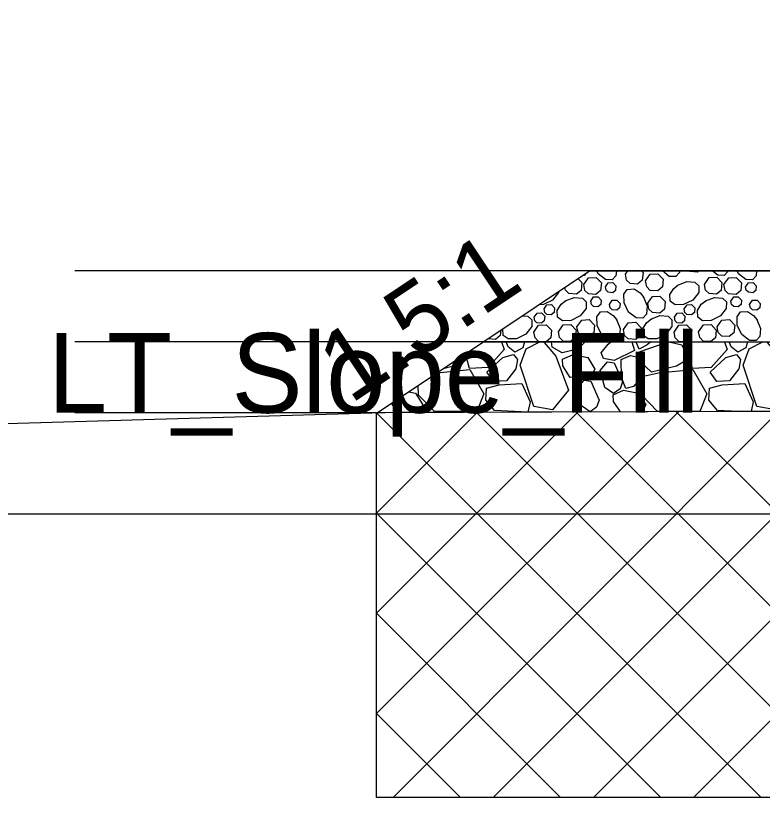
# Model space of a CAD drawing. Extents: x -14026 to 1303, y -10 to 9533.
# Drawn here: x 108.61 to 119.15, y 3996 to 4007.03 of the extents above; entities that cross this region are included whole.
import ezdxf

# ---------------------------------------------------------------- set-up
doc = ezdxf.new("R2010")
doc.units = 0
for name, color, linetype in [('Exist Cross Section Cell', 7, 'Continuous'), ('Exist XS Ground Line', 7, 'Continuous'), ('Old_Level_10', 7, 'Continuous'), ('Prop XS Side Slope Text', 7, 'Continuous'), ('Scratch_Level_0', 7, 'Continuous'), ('Scratch_Level_3', 7, 'Continuous'), ('Scratch_Level_5', 7, 'Continuous')]:
    doc.layers.add(name, color=color, linetype=linetype)

msp = doc.modelspace()

# ---------------------------------------------------------------- linework, layer by layer
at = {"layer": 'Exist Cross Section Cell'}
msp.add_line((0, 4000), (150, 4000), dxfattribs=at)
at = {"layer": 'Exist XS Ground Line'}
msp.add_lwpolyline([(103.803, 4001.139), (113.961, 4001.433), (121.109, 4001.453), (122.206, 4001.557), (124.865, 4002.502), (128.249, 4003.656), (131.147, 4004.565), (132.692, 4005.022), (133.861, 4005.345), (137.453, 4006.434), (141.559, 4006.646), (143.818, 4006.925), (150, 4006.975), (154.881, 4007.014), (166.19, 4007.028)], dxfattribs=at)
at = {"layer": 'Old_Level_10'}
for p, q in [((117.217, 4003.38), (117.249, 4003.426)), ((115.211, 4002.426), (124.649, 4002.426)), ((114.931, 4002.238), (114.955, 4002.182)), ((114.006, 4001.427), (113.915, 4001.561))]:
    msp.add_line(p, q, dxfattribs=at)
msp.add_lwpolyline([(121.109, 4001.453), (113.711, 4001.425), (116.711, 4003.426), (127.573, 4003.426), (122.206, 4001.557)], close=True, dxfattribs=at)
for points in [[(117.09, 4003.426), (117.084, 4003.358), (117.032, 4003.303), (116.938, 4003.305), (116.832, 4003.388), (116.813, 4003.426)], [(117.445, 4003.426), (117.466, 4003.404), (117.455, 4003.296), (117.389, 4003.24), (117.283, 4003.248), (117.233, 4003.296), (117.217, 4003.38)], [(117.983, 4003.426), (117.981, 4003.403), (117.929, 4003.348), (117.835, 4003.35), (117.738, 4003.426)], [(118.253, 4003.426), (118.234, 4003.41), (118.128, 4003.417), (118.12, 4003.426)], [(118.665, 4003.426), (118.664, 4003.419), (118.612, 4003.364), (118.519, 4003.366), (118.442, 4003.426)], [(119.069, 4003.426), (119.063, 4003.358), (119.011, 4003.303), (118.917, 4003.305), (118.811, 4003.388), (118.792, 4003.426)], [(116.548, 4003.317), (116.602, 4003.262), (116.591, 4003.153), (116.525, 4003.098), (116.419, 4003.106), (116.369, 4003.154), (116.361, 4003.192)], [(116.658, 4003.39), (116.634, 4003.364), (116.62, 4003.364)], [(116.629, 4003.233), (116.696, 4003.329), (116.804, 4003.335), (116.878, 4003.258), (116.867, 4003.149), (116.801, 4003.094), (116.695, 4003.102), (116.645, 4003.15), (116.629, 4003.233)], [(117.501, 4003.285), (117.568, 4003.38), (117.675, 4003.386), (117.75, 4003.309), (117.739, 4003.201), (117.673, 4003.145), (117.567, 4003.153), (117.517, 4003.201), (117.501, 4003.285)], [(118.331, 4003.237), (118.398, 4003.333), (118.506, 4003.339), (118.58, 4003.262), (118.57, 4003.153), (118.503, 4003.098), (118.397, 4003.106), (118.347, 4003.154), (118.331, 4003.237)], [(118.608, 4003.233), (118.675, 4003.329), (118.782, 4003.335), (118.857, 4003.258), (118.846, 4003.149), (118.78, 4003.094), (118.674, 4003.102), (118.624, 4003.15), (118.608, 4003.233)], [(116.935, 4003.204), (116.975, 4003.261), (117.04, 4003.265), (117.084, 4003.218), (117.078, 4003.153), (117.038, 4003.12), (116.975, 4003.125), (116.945, 4003.154), (116.935, 4003.204)], [(117.956, 4003.228), (118.082, 4003.278), (118.197, 4003.268), (118.252, 4003.216), (118.251, 4003.122), (118.167, 4003.016), (118.038, 4002.951), (117.917, 4002.949), (117.849, 4002.998), (117.842, 4003.095), (117.898, 4003.181), (117.961, 4003.232)], [(118.914, 4003.204), (118.954, 4003.261), (119.018, 4003.265), (119.063, 4003.218), (119.057, 4003.153), (119.017, 4003.12), (118.953, 4003.125), (118.923, 4003.154), (118.914, 4003.204)], [(116.272, 4003.133), (116.272, 4003.122), (116.189, 4003.016), (116.06, 4002.951), (115.999, 4002.95)], [(117.474, 4003.058), (117.524, 4002.933), (117.514, 4002.817), (117.461, 4002.762), (117.368, 4002.764), (117.261, 4002.847), (117.197, 4002.976), (117.195, 4003.097), (117.243, 4003.166), (117.34, 4003.172), (117.426, 4003.117), (117.477, 4003.053)], [(116.368, 4003.004), (116.493, 4003.054), (116.609, 4003.044), (116.664, 4002.991), (116.662, 4002.898), (116.579, 4002.791), (116.45, 4002.727), (116.329, 4002.725), (116.26, 4002.773), (116.254, 4002.87), (116.309, 4002.956), (116.373, 4003.007)], [(116.727, 4003.002), (116.767, 4003.059), (116.832, 4003.063), (116.876, 4003.016), (116.87, 4002.951), (116.83, 4002.918), (116.766, 4002.923), (116.737, 4002.952), (116.727, 4003.002)], [(116.992, 4002.955), (117.032, 4003.012), (117.096, 4003.016), (117.141, 4002.969), (117.135, 4002.904), (117.095, 4002.871), (117.031, 4002.876), (117.001, 4002.905), (116.992, 4002.955)], [(117.531, 4002.97), (117.598, 4003.066), (117.705, 4003.072), (117.78, 4002.994), (117.769, 4002.886), (117.703, 4002.831), (117.597, 4002.838), (117.547, 4002.887), (117.531, 4002.97)], [(118.346, 4003.004), (118.472, 4003.054), (118.588, 4003.044), (118.643, 4002.991), (118.641, 4002.898), (118.557, 4002.791), (118.429, 4002.727), (118.307, 4002.725), (118.239, 4002.773), (118.233, 4002.87), (118.288, 4002.956), (118.351, 4003.007)], [(118.706, 4003.002), (118.746, 4003.059), (118.81, 4003.063), (118.855, 4003.016), (118.849, 4002.951), (118.809, 4002.918), (118.745, 4002.923), (118.715, 4002.952), (118.706, 4003.002)], [(118.97, 4002.955), (119.011, 4003.012), (119.075, 4003.016), (119.12, 4002.969), (119.113, 4002.904), (119.074, 4002.871), (119.01, 4002.876), (118.98, 4002.905), (118.97, 4002.955)], [(116.068, 4002.891), (116.108, 4002.949), (116.173, 4002.953), (116.217, 4002.906), (116.211, 4002.841), (116.171, 4002.808), (116.108, 4002.813), (116.078, 4002.842), (116.068, 4002.891)], [(118.047, 4002.891), (118.087, 4002.949), (118.151, 4002.953), (118.196, 4002.906), (118.19, 4002.841), (118.15, 4002.808), (118.086, 4002.813), (118.056, 4002.842), (118.047, 4002.891)], [(115.764, 4002.794), (115.84, 4002.787), (115.895, 4002.735), (115.894, 4002.642), (115.81, 4002.535), (115.681, 4002.471), (115.56, 4002.468), (115.492, 4002.517), (115.486, 4002.608)], [(115.929, 4002.775), (115.97, 4002.832), (116.034, 4002.836), (116.079, 4002.789), (116.072, 4002.724), (116.033, 4002.691), (115.969, 4002.696), (115.939, 4002.725), (115.929, 4002.775)], [(117.093, 4002.741), (117.143, 4002.615), (117.133, 4002.5), (117.081, 4002.445), (116.987, 4002.447), (116.881, 4002.53), (116.816, 4002.659), (116.814, 4002.78), (116.863, 4002.849), (116.959, 4002.855), (117.046, 4002.8), (117.096, 4002.736)], [(117.578, 4002.748), (117.704, 4002.797), (117.819, 4002.787), (117.874, 4002.735), (117.872, 4002.642), (117.789, 4002.535), (117.66, 4002.471), (117.539, 4002.468), (117.47, 4002.517), (117.464, 4002.614), (117.519, 4002.7), (117.583, 4002.751)], [(117.908, 4002.775), (117.948, 4002.832), (118.013, 4002.836), (118.057, 4002.789), (118.051, 4002.724), (118.011, 4002.691), (117.948, 4002.696), (117.918, 4002.725), (117.908, 4002.775)], [(119.072, 4002.741), (119.122, 4002.615), (119.112, 4002.5), (119.06, 4002.445), (118.966, 4002.447), (118.859, 4002.53), (118.795, 4002.659), (118.793, 4002.78), (118.841, 4002.849), (118.938, 4002.855), (119.025, 4002.8), (119.075, 4002.736)], [(115.925, 4002.565), (115.992, 4002.66), (116.099, 4002.666), (116.174, 4002.589), (116.163, 4002.481), (116.097, 4002.426), (115.991, 4002.433), (115.941, 4002.482), (115.925, 4002.565)], [(116.272, 4002.569), (116.339, 4002.664), (116.446, 4002.67), (116.521, 4002.593), (116.51, 4002.485), (116.444, 4002.429), (116.338, 4002.437), (116.288, 4002.486), (116.272, 4002.569)], [(116.532, 4002.639), (116.6, 4002.734), (116.707, 4002.741), (116.782, 4002.663), (116.771, 4002.555), (116.704, 4002.5), (116.598, 4002.507), (116.549, 4002.556), (116.532, 4002.639)], [(117.19, 4002.6), (117.257, 4002.696), (117.365, 4002.702), (117.439, 4002.625), (117.428, 4002.516), (117.362, 4002.461), (117.256, 4002.469), (117.206, 4002.517), (117.19, 4002.6)], [(117.903, 4002.565), (117.971, 4002.66), (118.078, 4002.666), (118.153, 4002.589), (118.142, 4002.481), (118.076, 4002.426), (117.97, 4002.433), (117.92, 4002.482), (117.904, 4002.565)], [(118.25, 4002.569), (118.318, 4002.664), (118.425, 4002.67), (118.5, 4002.593), (118.489, 4002.485), (118.422, 4002.429), (118.316, 4002.437), (118.267, 4002.486), (118.25, 4002.569)], [(118.511, 4002.639), (118.578, 4002.734), (118.686, 4002.741), (118.76, 4002.663), (118.749, 4002.555), (118.683, 4002.5), (118.577, 4002.507), (118.527, 4002.556), (118.511, 4002.639)], [(115.457, 4002.589), (115.45, 4002.516), (115.383, 4002.461), (115.277, 4002.469), (115.277, 4002.469)], [(115.468, 4002.426), (115.507, 4002.319), (115.28, 4002.066), (115.018, 4002.049), (114.958, 4002.257)], [(115.657, 4002.281), (115.561, 4002.358), (115.536, 4002.426)], [(115.792, 4002.426), (115.768, 4002.342), (115.657, 4002.281)], [(116.069, 4002.419), (116.233, 4002.225), (116.415, 4001.745), (116.189, 4001.467), (115.924, 4001.512), (115.732, 4002.099), (115.816, 4002.327), (116.007, 4002.426)], [(116.651, 4002.426), (116.54, 4002.322), (116.323, 4002.27), (116.182, 4002.351), (116.176, 4002.426)], [(116.873, 4002.273), (116.974, 4002.395), (117.013, 4002.426)], [(117.307, 4002.426), (117.347, 4002.304), (117.06, 4002.162), (116.909, 4002.192), (116.873, 4002.273)], [(117.413, 4002.321), (117.372, 4002.413), (117.366, 4002.426)], [(117.576, 4002.426), (117.524, 4002.382), (117.413, 4002.321)], [(118.103, 4002.182), (117.938, 4002.082), (117.585, 4001.999), (117.429, 4002.143), (117.423, 4002.292), (117.818, 4002.426)], [(117.833, 4002.426), (118.013, 4002.385), (118.103, 4002.182)], [(118.616, 4002.426), (118.655, 4002.319), (118.427, 4002.066), (118.165, 4002.049), (118.058, 4002.426)], [(118.805, 4002.281), (118.708, 4002.358), (118.683, 4002.426)], [(118.939, 4002.426), (118.915, 4002.342), (118.805, 4002.281)], [(119.217, 4002.419), (119.381, 4002.225), (119.563, 4001.745), (119.336, 4001.467), (119.072, 4001.512), (118.879, 4002.099), (118.964, 4002.327), (119.155, 4002.426)], [(115.695, 4002.176), (115.672, 4002.045), (115.538, 4001.876), (115.361, 4001.868), (115.263, 4001.998), (115.485, 4002.205), (115.636, 4002.249), (115.695, 4002.176)], [(116.33, 4002.183), (116.478, 4002.246), (116.686, 4002.204), (116.786, 4002.039), (116.734, 4001.943), (116.435, 4001.925), (116.334, 4002.09), (116.33, 4002.183)], [(117.223, 4001.768), (117.162, 4001.922), (117.157, 4002.177), (117.29, 4002.236), (117.375, 4002.213), (117.413, 4001.89), (117.329, 4001.797), (117.223, 4001.768)], [(118.843, 4002.176), (118.819, 4002.045), (118.685, 4001.876), (118.509, 4001.868), (118.411, 4001.998), (118.632, 4002.205), (118.784, 4002.249), (118.843, 4002.176)], [(114.955, 4002.182), (114.791, 4002.082), (114.644, 4002.047)], [(117.05, 4001.698), (116.928, 4001.781), (116.861, 4002.022), (116.963, 4002.145), (117.057, 4002.13), (117.175, 4001.86), (117.141, 4001.765), (117.05, 4001.698)], [(114.559, 4001.991), (115.023, 4002.034), (115.218, 4001.691), (115.122, 4001.443), (114.521, 4001.444), (114.299, 4001.673), (114.29, 4001.812)], [(117.43, 4001.935), (117.684, 4001.989), (118.17, 4002.034), (118.366, 4001.691), (118.269, 4001.443), (117.669, 4001.444), (117.447, 4001.673), (117.43, 4001.935)], [(116.72, 4001.44), (116.598, 4001.523), (116.532, 4001.764), (116.633, 4001.887), (116.728, 4001.872), (116.845, 4001.602), (116.811, 4001.506), (116.72, 4001.44)], [(115.257, 4001.774), (115.436, 4001.819), (115.755, 4001.838), (115.871, 4001.58), (115.84, 4001.435), (115.37, 4001.46), (115.245, 4001.605), (115.257, 4001.774)], [(118.805, 4001.444), (118.517, 4001.46), (118.393, 4001.605), (118.404, 4001.774)], [(118.404, 4001.774), (118.584, 4001.819), (118.902, 4001.838), (119.019, 4001.58), (118.99, 4001.445)], [(114.158, 4001.723), (114.252, 4001.704), (114.359, 4001.54), (114.306, 4001.444), (114.026, 4001.427)], [(117.044, 4001.677), (117.192, 4001.746), (117.4, 4001.704), (117.506, 4001.54), (117.454, 4001.444), (117.378, 4001.439)], [(117.146, 4001.438), (117.048, 4001.584), (117.044, 4001.677)]]:
    msp.add_lwpolyline(points, dxfattribs=at)
at = {"layer": 'Scratch_Level_3'}
for p, q in [((127.573, 4003.426), (109.446, 4003.426)), ((116.708, 4002.426), (109.446, 4002.426)), ((113.705, 4001.426), (109.446, 4001.426))]:
    msp.add_line(p, q, dxfattribs=at)
at = {"layer": 'Scratch_Level_5'}
for p, q in [((113.705, 3997.183), (117.964, 4001.441)), ((113.705, 3998.597), (116.544, 4001.436)), ((113.705, 4000.011), (115.125, 4001.431)), ((113.705, 4001.426), (119.131, 3996)), ((113.937, 3996), (119.383, 4001.447)), ((115.114, 4001.431), (120.545, 3996)), ((115.351, 3996), (120.803, 4001.452)), ((116.523, 4001.436), (121.959, 3996)), ((116.765, 3996), (122.206, 4001.44)), ((117.932, 4001.441), (122.206, 3997.168)), ((113.705, 4000.011), (117.717, 3996)), ((118.179, 3996), (122.206, 4000.026)), ((113.705, 3998.597), (116.302, 3996)), ((113.705, 3997.183), (114.888, 3996))]:
    msp.add_line(p, q, dxfattribs=at)
msp.add_lwpolyline([(122.206, 4001.557), (122.206, 3996), (113.705, 3996), (113.705, 4001.426), (113.961, 4001.433), (121.109, 4001.453)], close=True, dxfattribs=at)

# ---------------------------------------------------------------- texts
at = {"layer": 'Prop XS Side Slope Text'}
msp.add_text('1.5:1', height=1, rotation=33.6901, dxfattribs=at).set_placement((113.336, 4001.541))
at = {"layer": 'Scratch_Level_0'}
msp.add_text('LT_Slope_Fill', height=1.125, dxfattribs=at).set_placement((109.065, 4001.426))

doc.saveas('drawing.dxf')
